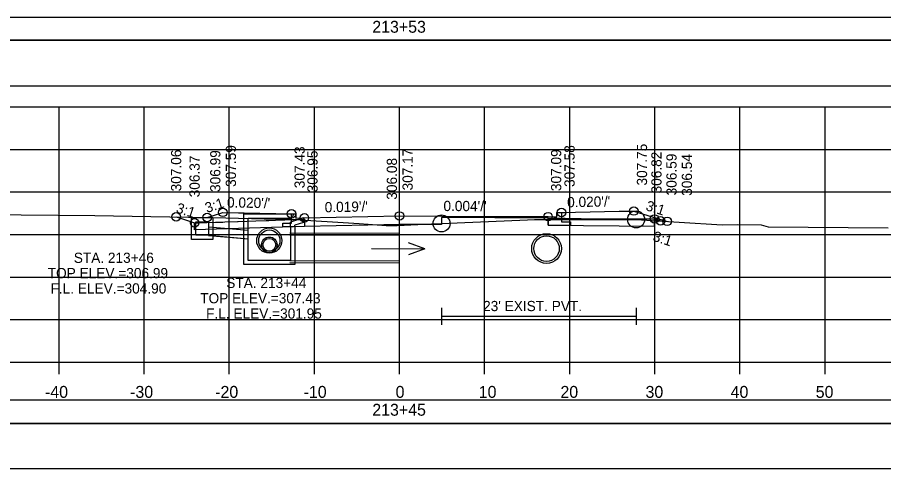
# Model space of a CAD drawing. Extents: x 1370538 to 1372872, y 376220 to 381127.
# Drawn here: x 1371663.7 to 1371765.5, y 379111.1 to 379164.1 of the extents above; entities that cross this region are included whole.
import ezdxf

# ---------------------------------------------------------------- set-up
doc = ezdxf.new("R2010")
doc.units = 0
for name, color, linetype in [('R_Border', 7, 'Continuous'), ('R_Border PE', 7, 'Continuous'), ('R_Border Prem', 7, 'Continuous'), ('R_Dimension', 7, 'Continuous'), ('R_Fin Surface', 7, 'Continuous'), ('R_Grid', 7, 'Continuous'), ('R_Horz Alg Annot', 7, 'Continuous'), ('R_No Plot', 7, 'Continuous'), ('R_Water', 7, 'Continuous'), ('R_Water Annot', 7, 'Continuous'), ('R_Xsect Elev', 7, 'Continuous'), ('R_Xsect Slope', 7, 'Continuous'), ('T_Detection Zones', 7, 'Continuous')]:
    doc.layers.add(name, color=color, linetype=linetype)

msp = doc.modelspace()

# ---------------------------------------------------------------- linework, layer by layer
at = {"layer": 'R_Border'}
for p, q in [((1371713.57, 379130), (1371713.57, 379128)), ((1371736.43, 379130), (1371736.43, 379128)), ((1371713.57, 379129), (1371736.43, 379129))]:
    msp.add_line(p, q, dxfattribs=at)
for points in [[(1371708.63, 379139.78), (1371697.45, 379139.56), (1371694.93, 379139.51), (1371694.93, 379139.93), (1371695.94, 379139.95), (1371695.94, 379141.04)], [(1371727.66, 379141.19), (1371727.66, 379140.09), (1371728.72, 379140.08), (1371728.72, 379139.66), (1371726.08, 379139.7), (1371726.08, 379139.7), (1371726.08, 379140.53), (1371713.57, 379140.59), (1371713.57, 379139.76), (1371708.63, 379139.78)]]:
    msp.add_lwpolyline(points, dxfattribs=at)
at = {"layer": 'R_Border Prem'}
for p, q in [((1371558.63, 379123.61), (1371858.63, 379123.61)), ((1371668.63, 379122.21), (1371668.63, 379123.61)), ((1371678.63, 379122.21), (1371678.63, 379123.61)), ((1371688.63, 379122.21), (1371688.63, 379123.61)), ((1371698.63, 379122.21), (1371698.63, 379123.61)), ((1371708.63, 379122.21), (1371708.63, 379123.61)), ((1371718.63, 379122.21), (1371718.63, 379123.61)), ((1371728.63, 379122.21), (1371728.63, 379123.61)), ((1371738.63, 379122.21), (1371738.63, 379123.61)), ((1371748.63, 379122.21), (1371748.63, 379123.61)), ((1371758.63, 379122.21), (1371758.63, 379123.61))]:
    msp.add_line(p, q, dxfattribs=at)
at = {"layer": 'R_Dimension'}
msp.add_lwpolyline([(1371654.31, 379140.97), (1371664.18, 379140.9), (1371672.84, 379140.84), (1371688.2, 379140.56), (1371694.21, 379140.4), (1371695.72, 379140.4), (1371703.87, 379139.88), (1371707.06, 379139.66), (1371707.2, 379139.66), (1371707.25, 379139.66), (1371707.65, 379139.66), (1371708.36, 379139.68), (1371712.39, 379139.85), (1371713.57, 379139.9), (1371723.66, 379140.32), (1371724.5, 379140.36), (1371734.92, 379140.37), (1371736.43, 379140.38), (1371746.53, 379139.75), (1371746.54, 379139.75), (1371746.56, 379139.75), (1371748.39, 379139.79), (1371748.4, 379139.79), (1371748.4, 379139.79), (1371751.13, 379139.73), (1371751.97, 379139.51), (1371766.05, 379139.37)], dxfattribs=at)
at = {"layer": 'R_Fin Surface'}
for points in [[(1371686.03, 379140.6), (1371686.67, 379140.81), (1371687.86, 379141.2), (1371689.72, 379141.16), (1371690.14, 379141.16), (1371690.37, 379141.15), (1371695.94, 379141.04), (1371696.01, 379141.04), (1371696.44, 379141.04), (1371696.44, 379141), (1371696.44, 379140.54), (1371697.18, 379140.56), (1371697.23, 379140.56), (1371697.45, 379140.56), (1371708.63, 379140.78)], [(1371708.63, 379140.78), (1371713.66, 379140.75), (1371719.6, 379140.72), (1371726.08, 379140.7), (1371726.77, 379140.69), (1371727.13, 379140.69), (1371727.13, 379140.95), (1371727.13, 379141.19), (1371727.34, 379141.19), (1371727.66, 379141.19), (1371728.02, 379141.19), (1371728.1, 379141.2), (1371729.31, 379141.22), (1371734.44, 379141.33), (1371736.17, 379141.36), (1371737.81, 379140.85), (1371740.08, 379140.15)]]:
    msp.add_lwpolyline(points, dxfattribs=at)
at = {"layer": 'R_Grid'}
for p, q in [((1371558.63, 379153.61), (1371858.63, 379153.61)), ((1371668.63, 379123.61), (1371668.63, 379153.61)), ((1371678.63, 379123.61), (1371678.63, 379153.61)), ((1371688.63, 379123.61), (1371688.63, 379153.61)), ((1371698.63, 379123.61), (1371698.63, 379153.61)), ((1371708.63, 379123.61), (1371708.63, 379153.61)), ((1371718.63, 379123.61), (1371718.63, 379153.61)), ((1371728.63, 379123.61), (1371728.63, 379153.61)), ((1371738.63, 379123.61), (1371738.63, 379153.61)), ((1371748.63, 379123.61), (1371748.63, 379153.61)), ((1371758.63, 379123.61), (1371758.63, 379153.61)), ((1371558.63, 379148.61), (1371858.63, 379148.61)), ((1371558.63, 379143.61), (1371858.63, 379143.61)), ((1371558.63, 379138.61), (1371858.63, 379138.61)), ((1371558.63, 379133.61), (1371858.63, 379133.61)), ((1371558.63, 379128.61), (1371858.63, 379128.61)), ((1371558.63, 379123.61), (1371858.63, 379123.61))]:
    msp.add_line(p, q, dxfattribs=at)
at = {"layer": 'R_Horz Alg Annot'}
for points in [[(1371682.38, 379140.67), (1371683.48, 379140.32), (1371684.55, 379139.97), (1371684.91, 379139.98), (1371685.02, 379139.99), (1371687, 379140.04), (1371687.86, 379140.07), (1371688.09, 379140.08), (1371689.61, 379140.13), (1371689.65, 379140.13), (1371691.76, 379140.2), (1371692.94, 379140.24), (1371693.27, 379140.25), (1371694.06, 379140.28), (1371697.31, 379140.39), (1371697.32, 379140.39), (1371697.45, 379140.39)], [(1371697.45, 379140.39), (1371697.45, 379139.56), (1371684.55, 379139.14), (1371684.55, 379139.97)], [(1371726.08, 379140.53), (1371728.1, 379140.51), (1371729.96, 379140.5), (1371734.44, 379140.45), (1371738.6, 379140.43), (1371739.18, 379140.24), (1371739.29, 379140.2)], [(1371726.08, 379140.53), (1371726.08, 379139.7), (1371738.6, 379139.6), (1371738.6, 379140.43)]]:
    msp.add_lwpolyline(points, dxfattribs=at)
at = {"layer": 'R_No Plot'}
for p, q in [((1371686.18, 379139.51), (1371690.9, 379139.11)), ((1371695.74, 379138.81), (1371708.63, 379138.76)), ((1371686.18, 379138.5), (1371690.9, 379138.1)), ((1371695.74, 379135.31), (1371708.63, 379135.26))]:
    msp.add_line(p, q, dxfattribs=at)
for centre, radius in [((1371687.86, 379141.2), 0.5), ((1371727.66, 379141.19), 0.5), ((1371736.17, 379141.36), 0.5), ((1371682.38, 379140.67), 0.5), ((1371686.03, 379140.6), 0.5), ((1371695.94, 379141.04), 0.5), ((1371697.45, 379140.56), 0.5), ((1371708.63, 379140.78), 0.5), ((1371708.63, 379140.78), 0.5), ((1371713.57, 379139.9), 1), ((1371726.08, 379140.7), 0.5), ((1371736.43, 379140.38), 1), ((1371738.6, 379140.43), 0.5), ((1371739.29, 379140.2), 0.5), ((1371740.08, 379140.15), 0.5), ((1371684.55, 379139.97), 0.5), ((1371693.33, 379137.89), 1.48), ((1371725.91, 379136.95), 1.75), ((1371693.33, 379137.39), 0.917)]:
    msp.add_circle(centre, radius, dxfattribs=at)
at = {"layer": 'R_Water'}
for p, q in [((1371690.33, 379141.04), (1371696.08, 379141.04)), ((1371690.33, 379139.54), (1371690.33, 379141.04)), ((1371696.17, 379140.88), (1371695.83, 379140.54)), ((1371697.33, 379140.56), (1371695.83, 379140.04)), ((1371696.17, 379140.88), (1371696.08, 379141.04)), ((1371690.83, 379139.54), (1371690.83, 379140.54)), ((1371690.83, 379140.54), (1371695.83, 379140.54)), ((1371695.83, 379139.54), (1371695.83, 379140.04)), ((1371697.33, 379140.03), (1371696.33, 379139.69)), ((1371696.33, 379139.54), (1371696.33, 379139.69)), ((1371686.18, 379139.51), (1371690.9, 379139.11)), ((1371695.74, 379138.56), (1371708.63, 379138.51)), ((1371686.18, 379138.51), (1371690.9, 379138.11)), ((1371695.74, 379135.56), (1371708.63, 379135.51))]:
    msp.add_line(p, q, dxfattribs=at)
for points in [[(1371551.2, 379156.09), (1371866.33, 379156.09), (1371866.33, 379161.42), (1371551.2, 379161.42)], [(1371685.45, 379140.6), (1371686.7, 379140.6), (1371686.7, 379138.01), (1371685.45, 379138.01), (1371684.2, 379138.01), (1371684.2, 379140.6)], [(1371685.45, 379140.1), (1371686.2, 379140.1), (1371686.2, 379138.51), (1371685.45, 379138.51), (1371684.7, 379138.51), (1371684.7, 379140.1)], [(1371551.2, 379111.09), (1371866.33, 379111.09), (1371866.33, 379116.41), (1371551.2, 379116.41)]]:
    msp.add_lwpolyline(points, close=True, dxfattribs=at)
for points in [[(1371697.33, 379140.03), (1371697.33, 379140.56)], [(1371696.33, 379139.54), (1371696.33, 379135.06), (1371693.33, 379135.06), (1371690.33, 379135.06), (1371690.33, 379139.54)], [(1371695.83, 379139.54), (1371695.83, 379135.56), (1371693.33, 379135.56), (1371690.83, 379135.56), (1371690.83, 379139.54)]]:
    msp.add_lwpolyline(points, dxfattribs=at)
for centre, radius in [((1371693.33, 379137.89), 1.25), ((1371693.33, 379137.39), 0.75), ((1371725.91, 379136.95), 1.5)]:
    msp.add_circle(centre, radius, dxfattribs=at)
at = {"layer": 'R_Water Annot'}
for p, q in [((1371711.61, 379136.92), (1371709.69, 379137.63)), ((1371705.32, 379136.94), (1371711.61, 379136.92)), ((1371711.61, 379136.92), (1371709.68, 379136.23))]:
    msp.add_line(p, q, dxfattribs=at)
at = {"layer": 'R_Xsect Elev'}
msp.add_line((1371708.63, 379139.69), (1371708.63, 379149.69), dxfattribs=at)
at = {"layer": 'T_Detection Zones'}
for points in [[(1371551.2, 379161.42), (1371866.33, 379161.42), (1371866.33, 379164.12), (1371551.2, 379164.12)], [(1371551.2, 379116.41), (1371866.33, 379116.41), (1371866.33, 379119.12), (1371551.2, 379119.12)]]:
    msp.add_lwpolyline(points, close=True, dxfattribs=at)

# ---------------------------------------------------------------- texts
at = {"layer": 'R_Border PE'}
for s, p in [('213+53', (1371705.43, 379162.31)), ('-40', (1371666.97, 379119.41)), ('-30', (1371676.97, 379119.41)), ('-20', (1371686.97, 379119.41)), ('-10', (1371697.36, 379119.41)), ('0', (1371708.17, 379119.41)), ('10', (1371717.94, 379119.41)), ('20', (1371727.54, 379119.41)), ('30', (1371737.54, 379119.41)), ('40', (1371747.54, 379119.41)), ('50', (1371757.54, 379119.41)), ('213+45', (1371705.43, 379117.31))]:
    msp.add_text(s, height=1.4, dxfattribs=at).set_placement(p)
at = {"layer": 'R_Water'}
msp.add_text("23' EXIST. PVT.", height=1.2, dxfattribs=at).set_placement((1371718.45, 379129.6))
at = {"layer": 'R_Water Annot'}
for s, p in [('STA. 213+46', (1371670.35, 379135.27)), ('TOP ELEV.=306.99', (1371667.29, 379133.47)), ('STA. 213+44', (1371688.27, 379132.32)), ('F.L. ELEV.=304.90', (1371667.62, 379131.67)), ('TOP ELEV.=307.43', (1371685.21, 379130.52)), ('F.L. ELEV.=301.95', (1371685.9, 379128.72))]:
    msp.add_text(s, height=1.2, dxfattribs=at).set_placement(p)
at = {"layer": 'R_Xsect Elev'}
for s, p in [('307.59', (1371689.41, 379144.2)), ('307.43', (1371697.49, 379144.04)), ('307.58', (1371729.21, 379144.19)), ('307.75', (1371737.72, 379144.36)), ('307.06', (1371682.98, 379143.67)), ('306.37', (1371685.15, 379142.97)), ('306.99', (1371687.58, 379143.6)), ('306.95', (1371699, 379143.56)), ('307.17', (1371710.18, 379143.78)), ('307.09', (1371727.63, 379143.7)), ('306.82', (1371739.42, 379143.43)), ('306.59', (1371741.19, 379143.2)), ('306.54', (1371743, 379143.15)), ('306.08', (1371708.33, 379142.69))]:
    msp.add_text(s, height=1.2, rotation=90, dxfattribs=at).set_placement(p)
at = {"layer": 'R_Xsect Slope'}
for s, rotation, p in [('3:1', 18.1963, (1371686, 379141.12)), ("0.020'/'", 358.8666, (1371688.35, 379141.79)), ("0.004'/'", 359.761, (1371713.79, 379141.36)), ("0.020'/'", 1.1839, (1371728.34, 379141.8)), ('3:1', 342.3153, (1371682.28, 379141.22)), ("0.019'/'", 1.0998, (1371699.85, 379141.21)), ('3:1', 342.7959, (1371737.48, 379141.48)), ('3:1', 341.8957, (1371738.31, 379137.9))]:
    msp.add_text(s, height=1.2, rotation=rotation, dxfattribs=at).set_placement(p)

doc.saveas('drawing.dxf')
